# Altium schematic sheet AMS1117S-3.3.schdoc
size 127 x 101 mm
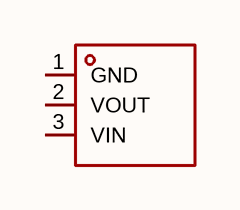
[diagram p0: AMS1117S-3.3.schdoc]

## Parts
U?  ams1117s-3.3  [SOT-89-3_L4.5-W2.5-P1.50-LS4.1-BR]  (value not drawn)

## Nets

Not connected (* = marked no-connect by the designer): U? 1(GND) 2(VOUT) 3(VIN)

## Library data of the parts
U? = ams1117s-3.3: 输出极性:正极;工作电压:30V;输出电压:3.3V;输出电流:1A;电源纹波抑制比(PSRR):70dB@(120Hz);输出类型:固定;; Manufacturer: JSMSEMI(杰盛微); AddInBom: yes; ModelId: 6db690b7897d4d18a30d90c1b89525ee; ModelName: SOT-89-3_L4.3-W2.5-H1.6-LS4.1-P1.50; ModelTransform: 161.417,169.291,0,180,0,0,-14.134,0,0; Output Configuration: 正极; Voltage - Supply: 30V; Output Voltage: 3.3V; Output Current: 1A; standby current: 3mA; Noise: 0.003%Vout; Output Type: 固定; Number of Outputs: 1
